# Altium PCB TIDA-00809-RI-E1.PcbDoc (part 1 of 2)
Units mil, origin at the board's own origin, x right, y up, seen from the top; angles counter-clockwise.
Board outline 5400 x 1000 mil, 2 copper layers (Top Layer, Bottom Layer), stack 62 mil thick; 167 components, 75 nets, 354 pads, 72 vias.
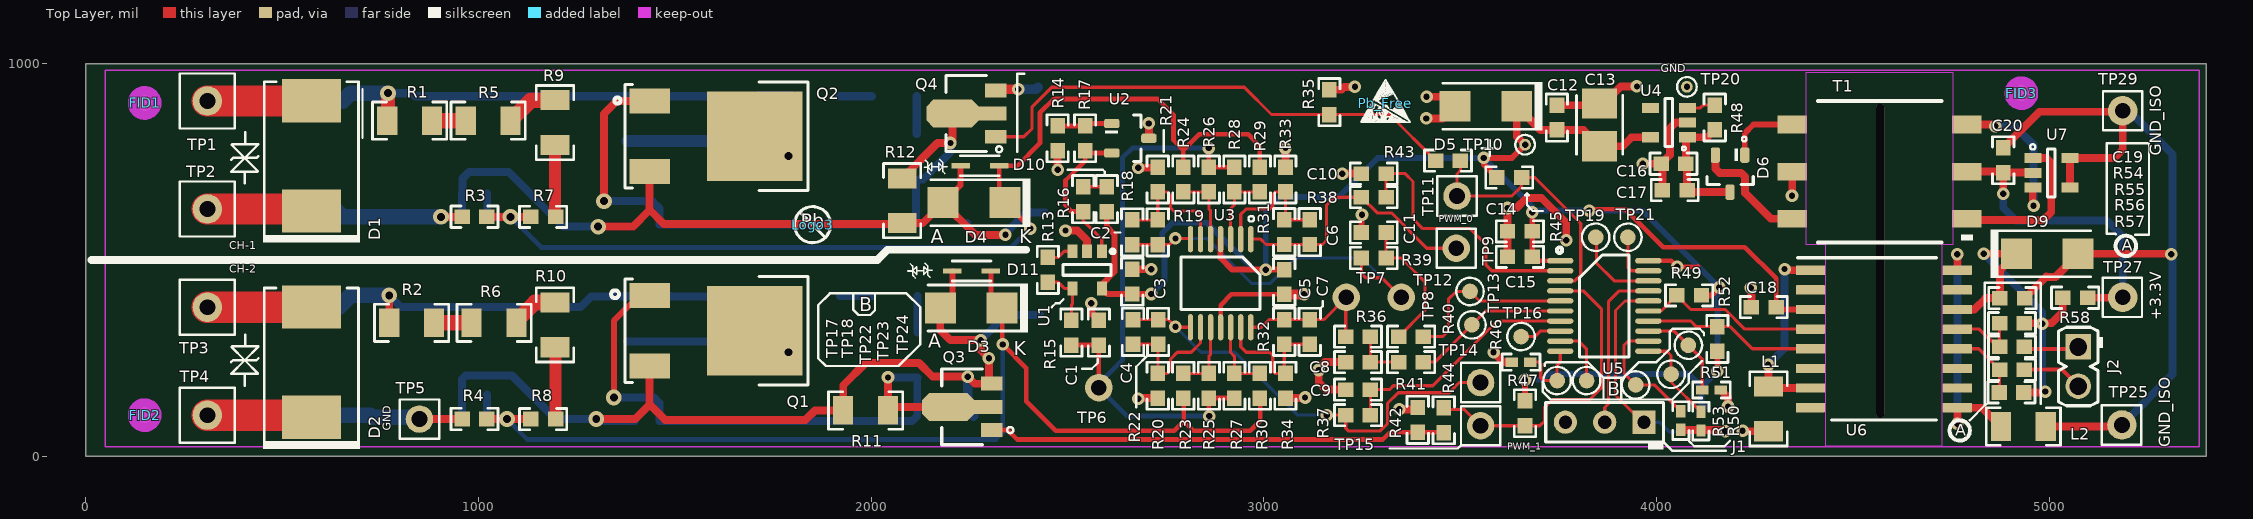
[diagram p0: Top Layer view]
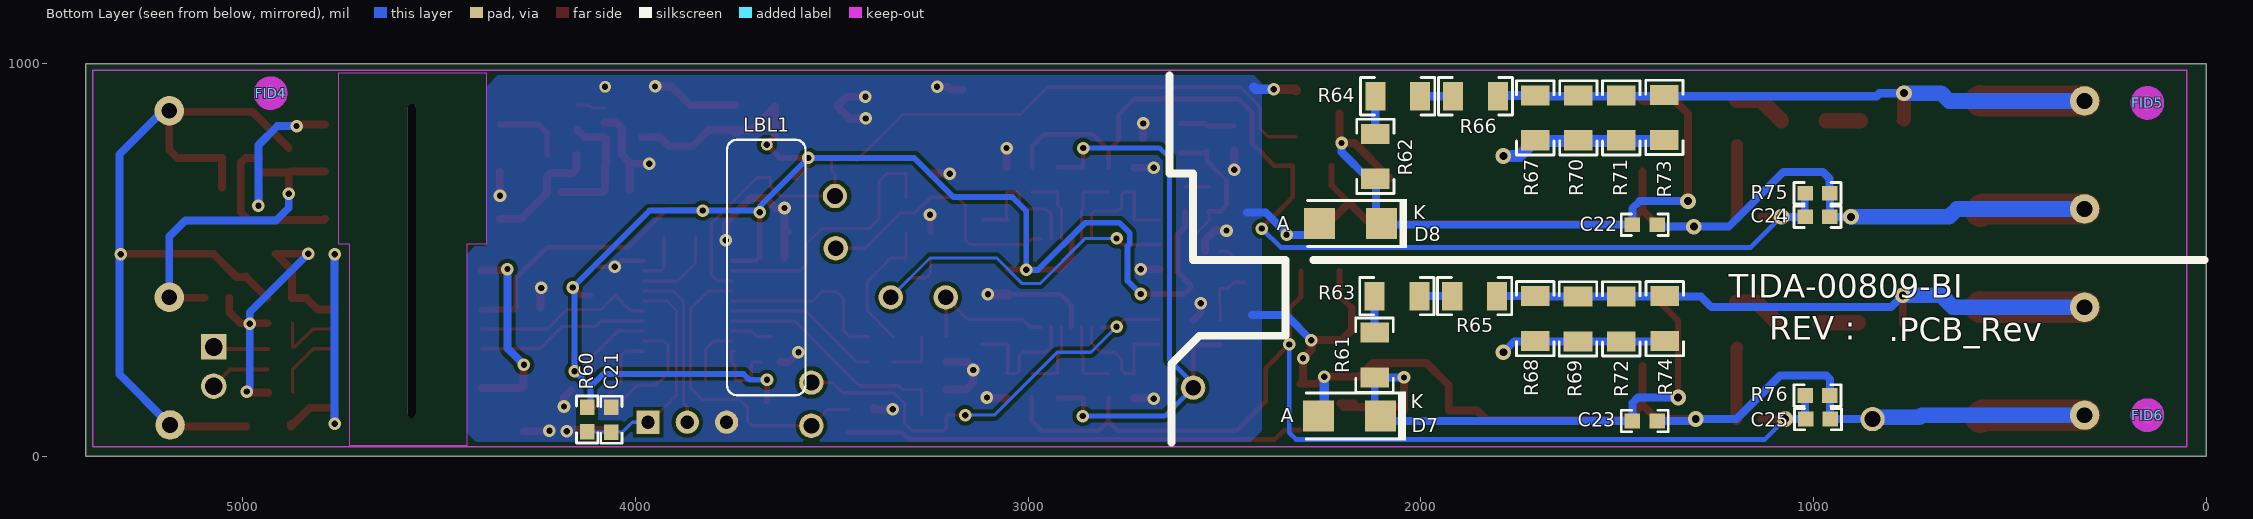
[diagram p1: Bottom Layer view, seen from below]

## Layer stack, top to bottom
Top Solder: solder mask 0.4, Solder Resist, Dk 3.5
Top Layer: signal copper 1.4
Dielectric1: core 59.2, FR-4, Dk 4.8
Bottom Layer: signal copper 1.4
Bottom Solder: solder mask 0.4, Solder Resist, Dk 3.5

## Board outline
0,0 5400,0 5400,1000 0,1000

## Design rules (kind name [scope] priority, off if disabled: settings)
AcuteAngle [All] p1: minimum=4.50000000000000E+0001 checktracksonly=FALSE
AssemblyTestPointUsage [All] p1: valid=2
Clearance "shape to track" [InPolygon vs IsTrack and IsSMTPin and IsVia] p1: gap=12
Clearance "Shape to Shape" [InPolygon vs InPolygon] p2: gap=25
Clearance "SMD to Via" [IsSMTPin vs IsVia] p3: gap=8
Clearance "Via to Via" [IsVia vs IsVia] p4: gap=12
Clearance [All] p5: gap=10
DiffPairsRouting [All] p1: maxlimit=100 minlimit=10 mostfreqgap=10 toplayer_minwidth=15 toplayer_maxwidth=15 toplayer_prefwidth=15 bottomlayer_minwidth=15 bottomlayer_maxwidth=15 bottomlayer_prefwidth=15 maxuncoupledlength=1000
FabricationTestPointUsage TestPointUsage [All] p1: valid=2 allowmultiple=FALSE
FabricationTestpoint Testpoint [All] p1: side=3 testpointundercomponent=TRUE minsize=40 maxsize=100 preferedsize=60 minholesize=0 maxholesize=40 preferedholesize=32 testpointgrid=1 allowsidetop=TRUE allowsidebottom=TRUE usegrid=TRUE gridtolerance=0.01
FanoutControl Fanout_LCC [IsLCC] p1: bgadir=Out bgaviamode=Centered fanoutstyle=Auto fanoutdirection=Alternating viagrid=1 // Fanout_LCC (Default Rule)
FanoutControl Fanout_BGA [IsBGA] p2: bgadir=Out bgaviamode=Centered fanoutstyle=Auto fanoutdirection=Alternating viagrid=1 // Fanout_BGA (Default Rule)
FanoutControl Fanout_Default [All] p4: bgadir=Out bgaviamode=Centered fanoutstyle=Auto fanoutdirection=Alternating viagrid=1 // Fanout_Default (Default Rule)
FanoutControl Fanout_Small [(CompPinCount < 5)] p5: bgadir=Out bgaviamode=Centered fanoutstyle=Auto fanoutdirection=OutThenIn viagrid=1 // Fanout_Small (Default Rule)
HoleSize [All] p1: absolutevalues=TRUE maxlimit=1000 minlimit=8 maxpercent=80.000 minpercent=20.000
MinimumAnnularRing [All] p1: minimumring=7
MinimumAnnularRing MinimumAnnularRing_ThermalPadVias [IsVia and InAnyComponent] p2: minimumring=5.91
MinimumSolderMaskSliver MinimumSolderMaskSliver_Logo [InComponentClass('Logo') vs InComponentClass('Logo')] p1: minsoldermaskwidth=0.7
MinimumSolderMaskSliver [All] p2: minsoldermaskwidth=3.94
PlaneConnect [All] p1: planeconnectstyle=Relief reliefexpansion=10 reliefentries=4 reliefconductorwidth=10 reliefairgap=10
PolygonConnect [All] p1: connectstyle=Direct reliefconductorwidth=10 reliefentries=4 polygonreliefangle="90 Angle" airgapwidth=10
RoutingVias ThermalPadVias [IsVia and InAnyComponent] p1: holewidth=8 width=20 viastyle="Through Hole" minholewidth=8 minwidth=20 maxholewidth=12 maxwidth=24
RoutingVias [All] p2: holewidth=16 width=32 viastyle="Through Hole" minholewidth=12 minwidth=26 maxholewidth=31.5 maxwidth=62.99
SMDToCorner [All] p1: distance=30000
ShortCircuit ShortCircuit_1 [InNet('GND') vs InNet('GND1')] p1: allowed=TRUE
SilkToSilkClearance [All] p1: silktosilkclearance=5
SilkToSolderMaskClearance SilkscreenOverComponentPads [IsPad] p1: minsilkscreentomaskgap=5 clearancetoexposedcopper=TRUE
SolderMaskExpansion [All] p1: expansion=2.5
UnpouredPolygon [All] p1: allowunpoured=FALSE
Width [All] p1: maxlimit=100 minlimit=8 preferedwidth=20 checkconnectedcopper=TRUE
15 further rules are at their usual default settings.

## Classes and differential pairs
component class "Pg3 MICROCONTROLLER": C12 C13 C14 C15 C16 C17 C18 C19 C20 C21 D5 D6 D9 J1 J2 L1 L2 R40 R41 R45 R46 R47 R48 R49 R50 R51 R52 R53 R54 R55 R56 R57 R58 R60 T1 TP10 TP12 TP13 TP16 TP17 TP18 TP19 TP21 TP22 TP23 TP24 TP25 TP27 TP29 U4 U5 U6 U7
component class Label: LBL1
component class AssemblyNote: ZZ1 ZZ2 ZZ3 ZZ4
component class Header: J1 J2
component class "Pg 5 Hardware_ANSI-B": !PCB1 FID1 FID2 FID3 FID4 FID5 FID6 LBL1 Logo3 Pb_Free ZZ1 ZZ2 ZZ3 ZZ4
component class FiducialMark: FID1 FID2 FID3 FID4 FID5 FID6
component class "Pg 4 BINARY INPUTS": C1 C2 C3 C4 C5 C6 C7 C8 C9 C10 C11 C22 C23 C24 C25 D1 D2 D3 D4 D7 D8 D10 D11 Q1 Q2 Q3 Q4 R1 R2 R3 R4 R5 R6 R7 R8 R9 R10 R11 R12 R13 R14 R15 R16 R17 R18 R19 R20 R21 R22 R23 R24 R25 R26 R27 R28 R29 R30 R31 R32 R33 R34 R35 R36 R37 R38 R39 R42 R43 R44 R61 R62 R63 R64 R65 R66 R67 R68 R69 R70 R71 R72 R73 R74 R75 R76 TP1 TP2 TP3 TP4 TP5 TP6 TP7 TP8 TP9 TP11 TP14 TP15 TP20 U1 U2 U3

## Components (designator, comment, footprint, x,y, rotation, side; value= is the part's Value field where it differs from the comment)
C1 "06033C104JAT2A" 0603 2580,315 r270 top
C2 "06035A101FAT2A" 0603 2665,570.5 r90 top
C3 "06033C104JAT2A" 0603 2665,445 r270 top
C4 "06035A101FAT2A" 0603 2667,317 r270 top
C5 "06033C104JAT2A" 0603 3052,444 r90 top
C6 "06035A101FAT2A" 0603 3117,571 r90 top
C7 "06035A101FAT2A" 0603 3117,317 r270 top
C8 "C1608C0G1E103J" 0603 3240,240 r0 top
C9 "C1608C0G1E103J" 0603 3240,170 r0 top
C10 "C1608C0G1E103J" 0603 3280,720 r0 top
C11 "C1608C0G1E103J" 0603 3280,570 r0 top
C12 "C0603C104K5RACTU" 0603 3746.36,862.64 r90 top
C13 "T491B106K016AT" 3528-21 3855,844 r90 top
C14 "C1608X7R1C105K" 0603 3652,573 r180 top
C15 "C0603C104K5RACTU" 0603 3652,508 r0 top
C16 "C0603C104K5RACTU" 0603 4043.32,745.02 r180 top
C17 "C1608X7R1C105K" 0603 4046.32,678.02 r180 top
C18 "C0603C104K5RACTU" 0603 4273,380 r0 top
C19 "C0603C104K5RACTU" 0603 4906,403 r0 top
C20 "C1608X7R1C105K" 0603 4883,754 r90 top
C21 "GRM188R71H471KA01D" 0603 4061.3,93.19 r90 bottom
C22 "UMK107AB7105KA-T" 0603 1430,590 r0 bottom
C23 "UMK107AB7105KA-T" 0603 1430,90 r0 bottom
C24 "C1608C0G1H102J" 0603 990,610 r0 bottom
C25 "C1608C0G1H102J" 0603 989,95 r0 bottom
D1 "SMCJ400CA" SMC 575,765 r90 top
D2 "SMCJ400CA" SMC 575,240 r90 top
D3 "PTZTE255.1B" SMA 2255,378 r180 top
D4 "PTZTE255.1B" SMA 2262,646 r180 top
D5 "PTZTE253.9B" SMA 3565.36,891.64 r180 top
D6 "BAT54C-7-F" SOT-23 4187.32,720.02 r270 top
D7 "PTZTE2515B" SMA 2182,103 r0 bottom
D8 "PTZTE2515B" SMA 2178.98,593 r0 bottom
D9 "PTZTE253.9B" SMA 4995,516 r0 top
D10 "PESD3V3L1BA" DIO_SOD323 2277,740 r180 top
D11 "PESD3V3L1BA" DIO_SOD323 2256,472 r180 top
FID1 "Fiducial" Fiducial10-20 150,900 r0 top
FID2 "Fiducial" Fiducial10-20 150,105 r0 top
FID3 "Fiducial" Fiducial10-20 4929,925 r0 top
FID4 "Fiducial" Fiducial10-20 4929,925 r180 bottom
FID5 "Fiducial" Fiducial10-20 150,900 r180 bottom
FID6 "Fiducial" Fiducial10-20 150,105 r180 bottom
J1 "800-10-003-10-001000" Mill-Max_800-10-003-10-001000 3868,87 r180 top
J2 "61300211121" WURTH_61300211121 5074,228.84 r270 top
L1 "HZ1206D102R-10" 1206 4285,121 r90 top
L2 "HZ1206D102R-10" 1206 4934,76 r0 top
LBL1 "Size: 0.65\" x 0.20 \"" Label_650x200 3667,481 r270 bottom
Logo3 "Pb-Free Symbol" Pb-Free_Overlay_Small 1851,590 r0 top
Pb_Free "ESD Susceptible" ESD_Overlay_small 3309,899 r0 top
Q1 "AOD2N60" DPAK_G 1570,320 r0 top
Q2 "AOD2N60" DPAK_G 1570,815 r0 top
Q3 "FCX458" SOT-89-3 2232,126 r180 top
Q4 "FCX458" SOT-89-3 2243,873 r180 top
R1 "RC1206FR-07100KL" 1206 825,855 r0 top
R2 "RC1206FR-07100KL" 1206 830,340 r0 top
R3 "RC0603FR-072K2L" 0603 990,610 r0 top
R4 "RC0603FR-072K2L" 0603 990,95 r0 top
R5 "RC1206FR-07100KL" 1206 1025,855 r0 top
R6 "RC1206FR-07100KL" 1206 1040,340 r0 top
R7 "RC0603JR-070RL" 0603 1165,610 r180 top
R8 "RC0603JR-070RL" 0603 1165,95 r180 top
R9 "RC1206FR-07100KL" 1206 1195,850 r270 top
R10 "RC1206FR-07100KL" 1206 1195,335 r270 top
R11 "CRCW1206100KFKEA" 1206 1986,117 r0 top
R12 "CRCW1206100KFKEA" 1206 2079,651 r90 top
R13 "RC0603JR-070RL" 0603 2450,475 r270 top
R14 "CRCW060310K0FKEA" 0603 2475,810 r90 top
R15 "CRCW0603100RFKEA" 0603 2510,315 r270 top
R16 "CRCW0603470RJNEA" 0603 2540,655 r90 top
R17 "CRCW060330K0JNEA" 0603 2545,810 r270 top
R18 "CRCW0603100RFKEA" 0603 2600,655 r90 top
R19 "CRCW0603160KFKEA" 0603 2730,570.5 r90 top
R20 "RC0603FR-0747KL" 0603 2730,180 r90 top
R21 "RC0603FR-0747KL" 0603 2730,705 r270 top
R22 "RC0603FR-0747KL" 0603 2731,317 r90 top
R23 "RC0603FR-0747KL" 0603 2795,180 r90 top
R24 "RC0603FR-0747KL" 0603 2795,705 r270 top
R25 "RC0603FR-0747KL" 0603 2860,180 r90 top
R26 "CRCW0603160KFKEA" 0603 2860,705 r270 top
R27 "CRCW0603160KFKEA" 0603 2925,180 r90 top
R28 "RC0603FR-0747KL" 0603 2925,705 r270 top
R29 "RC0603FR-0747KL" 0603 2990,705 r90 top
R30 "RC0603FR-0747KL" 0603 2990,180 r90 top
R31 "RC0603FR-0747KL" 0603 3052,571 r90 top
R32 "CRCW0603160KFKEA" 0603 3052,317 r270 top
R33 "RC0603FR-0747KL" 0603 3055,705 r90 top
R34 "RC0603FR-0747KL" 0603 3055,180 r90 top
R35 "CRCW0603100KFKEA" 0603 3167,902 r270 top
R36 "CRCW060310R0FKEA" 0603 3240,305 r0 top
R37 "CRCW060310R0FKEA" 0603 3240,105 r0 top
R38 "CRCW060310R0FKEA" 0603 3280,660 r0 top
R39 "CRCW060310R0FKEA" 0603 3280,505 r0 top
R40 "CRCW06030000Z0EA" 0603 3375,305 r0 top
R41 "CRCW06030000Z0EA" 0603 3375,240 r0 top
R42 "CRCW0603100KFKEA" 0603 3392,93 r270 top
R43 "CRCW06032K61FKEA" 0603 3469,753 r180 top
R44 "CRCW06032K61FKEA" 0603 3458,92 r270 top
R45 "CRCW060310K0FKEA" 0603 3625,710 r180 top
R46 "RC0402JR-070RL" 0402 3655,240 r0 top
R47 "CRCW060310K0FKEA" 0603 3665,110 r90 top
R48 "CRCW060310K0FKEA" 0603 4148.32,863.02 r270 top
R49 "CRCW06031K50FKEA" 0603 4083,410 r0 top
R50 "RC0402JR-070RL" 0402 4062,91 r90 top
R51 "RC0402JR-070RL" 0402 4140,169 r180 top
R52 "CRCW06031K50FKEA" 0603 4155,299 r270 top
R53 "RC0402JR-070RL" 0402 4113,89.62 r90 top
R54 "CRCW06031K50FKEA" 0603 4905,338.84 r0 top
R55 "CRCW06030000Z0EA" 0603 4905,278.84 r0 top
R56 "CRCW06030000Z0EA" 0603 4905,220.84 r0 top
R57 "CRCW06031K50FKEA" 0603 4904,162.84 r0 top
R58 "CRCW06030000Z0EA" 0603 5066,404 r0 top
R60 "RC0603JR-0747KL" 0603 4123,94 r90 bottom
R61 "RC1206FR-07100KL" 1206 2118,258 r90 bottom
R62 "RC1206FR-07100KL" 1206 2116,764 r270 bottom
R63 "RC1206FR-07100KL" 1206 2061,408 r180 bottom
R64 "RC1206FR-07100KL" 1206 2059,917 r0 bottom
R65 "RC1206FR-07100KL" 1206 1863,408 r0 bottom
R66 "RC1206FR-07100KL" 1206 1861,917 r0 bottom
R67 "MCR18ERTF1002" 1206 1709,862 r90 bottom
R68 "MCR18ERTF1002" 1206 1709,351 r90 bottom
R69 "MCR18ERTF1002" 1206 1600,350 r90 bottom
R70 "MCR18ERTF1002" 1206 1599,862 r90 bottom
R71 "MCR18ERTF1002" 1206 1490,862 r90 bottom
R72 "MCR18ERTF1002" 1206 1490,350 r90 bottom
R73 "MCR18ERTF1002" 1206 1380,863 r90 bottom
R74 "MCR18ERTF1002" 1206 1379,351 r90 bottom
R75 "RC0603FR-072K2L" 0603 990,670 r0 bottom
R76 "RC0603FR-072K2L" 0603 990,155 r0 bottom
T1 "#NAME?" Wurth_750313734 4568,725 r180 top
TP1 "TP-5001-BLACK" TH-40 310,905 r0 top
TP2 "TP-5001-BLACK" TH-40 310,630 r0 top
TP3 "TP-5001-BLACK" TH-40 310,380 r0 top
TP4 "TP-5001-BLACK" TH-40 310,105 r270 top
TP5 "TP-040_RND" TP-040_RND 850,95 r90 top
TP6 "TP-040_RND" TP-040_RND 2580,175 r90 top
TP7 "TP-040_RND" TP-040_RND 3210,405 r90 top
TP8 "TP-040_RND" TP-040_RND 3350,405 r90 top
TP9 "TP-040_RND" TP-040_RND 3490,530 r90 top
TP10 "TP1_PD40_D0.5_S50" TP1_PD40_D0.5_S50 3665.36,793.64 r90 top
TP11 "TP-040_RND" TP-040_RND 3492,663 r90 top
TP12 "PAD_230UM" PAD_230UM 3525,420 r90 top
TP13 "PAD_230UM" PAD_230UM 3530,335 r90 top
TP14 "TP-040_RND" TP-040_RND 3552,188 r90 top
TP15 "TP-040_RND" TP-040_RND 3552,78 r90 top
TP16 "PAD_230UM" PAD_230UM 3655,305 r90 top
TP17 "PAD_230UM" PAD_230UM 3747,193 r90 top
TP18 "PAD_230UM" PAD_230UM 3822,193 r90 top
TP19 "PAD_230UM" PAD_230UM 3845,558 r90 top
TP20 "TP1_PD40_D0.5_S50" TP1_PD40_D0.5_S50 4077.32,941.02 r90 top
TP21 "PAD_230UM" PAD_230UM 3927,558 r90 top
TP22 "PAD_230UM" PAD_230UM 3947,182 r90 top
TP23 "PAD_230UM" PAD_230UM 4037,209 r90 top
TP24 "PAD_230UM" PAD_230UM 4081,283 r90 top
TP25 "TP-5001-BLACK" TH-40 5185,80 r0 top
TP27 "TP-5001-BLACK" TH-40 5187,405 r0 top
TP29 "TP-5001-BLACK" TH-40 5187,880 r0 top
U1 "LMV551MF" MF05A_L 2550,475 r270 top
U2 "LM4041BIDBZ" SOT-23 2660,810 r0 top
U3 "LMV614MT" PW0014A_N 2890,440.98 r270 top
U4 "TPS70933DBVT" DBV0005A_N 4031.32,850.02 r180 top
U5 "MSP430G2332IPW20" PW0020A_N 3867,383 r0 top
U6 "ISO7820DWR" DW0016B_N 4579,299 r0 top
U7 "SN6501DBV" DBV0005A_N 5005.24,722 r0 top
ZZ1 "This Assembly Note is for PCB labels only" AssemblyNoteLabel -184,1762 r0 top
ZZ2 "These assemblies are ESD sensitive, ESD precautions shall be observed." AssemblyNote -184,1687 r0 top
ZZ3 "These assemblies must be clean and free from flux and all contaminants. Use of no clean flux is not acceptable." AssemblyNote -184,1602 r0 top
ZZ4 "These assemblies must comply with workmanship standards IPC-A-610 Class 2, unless otherwise specified." AssemblyNote -184,1527 r0 top

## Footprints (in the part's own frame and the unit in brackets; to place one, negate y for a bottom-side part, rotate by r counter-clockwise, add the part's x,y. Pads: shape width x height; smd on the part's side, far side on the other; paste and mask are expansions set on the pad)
0402 [mm] "0402 from SM-752 data"
  rect 0.8x0.6 smd: 1(-0.6,0) 2(0.6,0)
  silkscreen extent -1.22,-0.52 1.22,0.52, body extent -0.55,-0.3 0.55,0.3, height 0.6
0603 [mm] "0603 from SM-752 data"
  rect 1x0.95 smd: 1(-0.8,0) 2(0.8,0)
  silkscreen extent -1.52,-0.69 1.52,0.69, body extent -0.87,-0.47 0.87,0.47, height 0.85
1206 [mm] "1206 from SM-752 data"
  rect 1.3x1.85 smd: 1(-1.45,0) 2(1.45,0)
  silkscreen extent -2.4,-1.21 2.4,1.21, body extent -1.7,-0.9 1.7,0.9, height 1.35
3528-21 [mm] "Medium Density IPC, based on SM-782 section 8.4"
  rect 1.95x2.25 smd: 1(-1.375,0) 2(1.375,0)
  silkscreen extent -1.9,-1.5 1.9,1.5, body extent -1.85,-1.5 1.85,1.5, height 2.1
AssemblyNote [mil] "Assembly Note"
AssemblyNoteLabel [mil] "Assembly Note for PCB Labels"
DBV0005A_N [mm] "SOT23, 5-Leads, Body 2.9x1.6mm, Pitch 0.95mm, Lead Span 2.8mm, IPC Medium Density"
  rect 1.1x0.65 smd: 1(-1.2,0.95) 2(-1.2,0) 3(-1.2,-0.95) 4(1.2,-0.95) 5(1.2,0.95)
  silkscreen extent -0.25,-1.55 0.25,1.55, body extent -1.42,-1.46 1.42,1.46, height 1.08
DIO_SOD323 [mm] "TVS DIODE, SOD323, SMT"
  rect 1.2x0.35 smd: 1(-1.25,0) 2(1.25,0)
  silkscreen extent -1.25,-0.65 1.25,0.65, body extent -1.25,-0.63 1.25,0.63, height 1.1
DPAK_G [mm] "D-PAK, 3-Pads, Body 6.22x6.73mm (max), TO-252AA using nominal STEP model"
  rect 6.2x5.8 smd paste-2.9: D(3.4,0)
  rect 2.6x1.6 smd: G(-3.4,2.28) S(-3.4,-2.28)
  silkscreen extent -5.89,-3.5 6.83,3.5, body extent -3.86,-3.29 5.84,3.29, height 2.48
DW0016B_N [mm] "SOIC, 16-Leads, Body 10.5x7.6mm, Pitch 1.27mm, IPC Medium Density"
  rrect17% 1.9x0.6 smd: 1(-4.75,4.445) 2(-4.75,3.175) 3(-4.75,1.905) 4(-4.75,0.635) 5(-4.75,-0.635) 6(-4.75,-1.905) 7(-4.75,-3.175) 8(-4.75,-4.445) 9(4.75,-4.445) 10(4.75,-3.175) 11(4.75,-1.905) 12(4.75,-0.635) 13(4.75,0.635) 14(4.75,1.905) 15(4.75,3.175) 16(4.75,4.445)
  silkscreen extent -5.6,-5.25 3.4,5.25, body extent -5.17,-5.15 5.17,5.15, height 2.59
ESD_Overlay_small [mil]
  silkscreen extent -62,-48 64,61
Fiducial10-20 [mm]
  round 1 smd mask+0.5: 1(0,0)
  Top Layer keep-out circle w1.178: c0,0 r0.5
Label_650x200 [mil] "Thermal Transfer Label"
  silkscreen extent -325,-100 325,100, body extent -326,-101 326,101, height 1
MF05A_L [mm] "SOT23, 5-Leads, Body 2.9x1.6mm, Pitch 0.95mm, Lead Span 2.8mm, IPC High Density"
  rect 0.9x0.65 smd: 1(-1.2,0.95) 2(-1.2,0) 3(-1.2,-0.95) 4(1.2,-0.95) 5(1.2,0.95)
  silkscreen extent -1.32,-1.55 0.35,1.77, body extent -0.9,-1.55 0.9,1.55, height 1.19
Mill-Max_800-10-003-10-001000 [mm] "Mill-Max"
  rect 1.5x1.5 hole 0.85: 1(-2.54,0)
  round 1.5 hole 0.85: 2(0,0) 3(2.54,0)
  silkscreen extent -3.81,-1.27 3.81,1.78, body extent -3.81,-1.27 3.81,1.27, height 8.13
PAD_230UM [mil]
  round 40 smd: 1(0,0)
  silkscreen extent -35,-35 35,35
Pb-Free_Overlay_Small [mil]
  silkscreen extent -46,-46 46,46
PW0014A_N [mm] "TSOP, 14-Leads, Body 5x4.4mm, Pitch 0.65mm, IPC Medium Density"
  oval 1.7x0.35 smd: 1(-2.85,1.95) 2(-2.85,1.3) 3(-2.85,0.65) 4(-2.85,0) 5(-2.85,-0.65) 6(-2.85,-1.3) 7(-2.85,-1.95) 8(2.85,-1.95) 9(2.85,-1.3) 10(2.85,-0.65) 11(2.85,0) 12(2.85,0.65) 13(2.85,1.3) 14(2.85,1.95)
  silkscreen extent -1.7,-2.55 1.7,2.55, body extent -3.21,-2.5 3.21,2.5, height 0.98
PW0020A_N [mm] "TSOP, 20-Leads, Body 6.5x4.4mm, Pitch 0.65mm, IPC Medium Density"
  oval 1.7x0.35 smd: 1(-2.85,2.925) 2(-2.85,2.275) 3(-2.85,1.625) 4(-2.85,0.975) 5(-2.85,0.325) 6(-2.85,-0.325) 7(-2.85,-0.975) 8(-2.85,-1.625) 9(-2.85,-2.275) 10(-2.85,-2.925) 11(2.85,-2.925) 12(2.85,-2.275) 13(2.85,-1.625) 14(2.85,-0.975) 15(2.85,-0.325) 16(2.85,0.325) 17(2.85,0.975) 18(2.85,1.625) 19(2.85,2.275) 20(2.85,2.925)
  silkscreen extent -1.6,-3.3 1.6,3.3, body extent -3.21,-3.25 3.21,3.25, height 0.99
SMA [mm] "Molded Diode, 2-Leads, Body 4.3x2.6mm, IPC Medium Density, based on OnSemi component dimensions and land pattern"
  rect 2x2 smd: 1(-2,0) 2(2,0)
  silkscreen extent -3.66,-1.57 2.79,1.57, body extent -2.6,-1.3 2.6,1.3, height 2.42
SMC [mil] "Molded Diode, 2-Leads, Body 6.9x5.8mm, IPC Medium Density, based on OnSemi component dimensions and land patterns"
  rect 110x150 smd: 1(-140.49,0) 2(140.49,0)
  silkscreen extent -221,-123 189,124, body extent -156,-116 156,116, height 91
SOT-23 [mm] "SOT23, 3-Leads, Body 2.9x1.3mm, Pitch 0.95mm, Lead Span 2.5mm, IPC Medium Density"
  rrect50% 1x0.6 smd: 1(-1.2,0.95) 2(-1.2,-0.95) 3(1.2,0)
  silkscreen extent -1.62,-1.5 0.7,1.5, body extent -1.16,-1.45 1.21,1.45, height 1
SOT-89-3 [mm] "SOT, 3-Leads, Body 4.6 x 2.6 mm, Pitch 1.5mm"
  rect 1.4x0.9 smd: 1(-1.9,1.5) 3(-1.9,-1.5)
  rect 1.8x0.9 smd: 2(-1.7,0)
  oct 3.4x1.8 smd: 4(0.9,0)
  silkscreen extent -1.3,-2.45 1.33,2.45, body extent -2.42,-2.28 1.83,2.32, height 1.62
TH-40 [mil]
  round 75 hole 40: 1(0,0)
TP1_PD40_D0.5_S50 [mil]
  round 30 hole 16: 1(0,0)
  silkscreen extent -25,-25 25,25
TP-040_RND [mil]
  round 70 / inner round 62 / far side round 62 hole 40: 1(0,0)
Wurth_750313734 [mil]
  rect 75x45 smd: 1(-222.5,120) 2(-222.5,0) 3(-222.5,-120) 4(222.5,-120) 5(222.5,0) 6(222.5,120)
  silkscreen extent -238,-180 157,180, body extent -240,-180 157,180, height 300
WURTH_61300211121 [mm] "Header, 2.54mm, 2x1, TH"
  rect 1.65x1.65 hole 1.15: 1(-1.27,0)
  round 1.65 hole 1.15: 2(1.27,0)
  silkscreen extent -2.54,-1.27 2.54,1.6, body extent -2.54,-1.27 2.54,1.27, height 8.54

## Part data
C1 C3 C5: "CAP, CERM, 0.1uF, 25V, +/-5%, X7R, 0603"
C2 C4 C6 C7: "CAP, CERM, 100pF, 50V, +/-1%, C0G/NP0, 0603"
C8 C9 C10 C11: "CAP, CERM, 0.01uF, 25V, +/-5%, C0G/NP0, 0603"
C12 C15 C16 C18 C19: "CAP, CERM, 0.1uF, 50V, +/-10%, X7R, 0603"
C13: library part 293D106X9016B2TE3, "CAP, TA, 10 µF, 16 V, +/- 10%, 2 ohm, SMD"
C14 C17 C20: "CAP, CERM, 1uF, 16V, +/-10%, X7R, 0603"
C21: "CAP, CERM, 470 pF, 50 V, +/- 10%, X7R, 0603"
C22 C23: "CAP, CERM, 1 µF, 50 V, +/- 10%, X7R, 0603"
C24 C25: "CAP, CERM, 1000pF, 50V, +/-5%, C0G/NP0, 0603"
D1 D2: library part SMCJ15CA, "TVS DIODE 400VWM 648VC SMC"
D3 D4: library part BZT52C3V3T-7, "DIODE ZENER 5.4V 1W PMDS"
D5 D9: library part PTZTE255.6B, "DIODE ZENER 4.1V 1W PMDS"
D6: "Diode, Schottky, 30V, 0.2A, SOT-23"
D7 D8: library part BZT52C3V3T-7, "DIODE ZENER 15.4V 1W PMDS"
D10 D11: "DIODE, TVS, BIDIRECTIONAL, 3.3VWM, 26VC, SOD323"
FID1 FID2 FID3 FID4 FID5 FID6: "Fiducial mark.  There is nothing to buy or mount."
J1: "Header, 100mil, 3x1, TH"
J2: "Header, 2.54 mm, 2x1, Gold, TH"
L1 L2: "Ferrite Bead, 1000 ohm @ 100 MHz, 0.4 A, 1206"
LBL1: library part THT-14-423-10, "Thermal Transfer Printable Labels, 0.650\" W x 0.200\" H - 10,000 per roll"
Logo3: library part Pb-Free
Pb_Free: library part ESD_Susceptible, "ESD Susceptible Symbol"
Q1 Q2: library part DN2450K4-G, "MOSFET N-CH 600V 2A TO252"
Q3 Q4: library part "FCX458TA, Diodes Inc.", "Transistor, NPN, 400V, 500mA, SOT-89"
R1 R2 R5 R6 R9 R10 R61 R62 R63 R64 R65 R66: "RES, 100 k, 1%, 0.25 W, 1206"
R3 R4 R75 R76: "RES, 2.20 k, 1%, 0.1 W, 0603"
R7 R8 R13 R40 R41 R55 R56 R58: "RES, 0, 5%, 0.1 W, 0603"
R11 R12: "RES, 100k ohm, 1%, 0.25W, 1206"
R14 R45 R47 R48: "RES, 10.0k ohm, 1%, 0.1W, 0603"
R15 R18: "RES, 100 ohm, 1%, 0.1W, 0603"
R16: "RES, 470 ohm, 5%, 0.1W, 0603"
R17: "RES, 30k ohm, 5%, 0.1W, 0603"
R19 R26 R27 R32: "RES, 160 k, 1%, 0.1 W, 0603"
R20 R21 R22 R23 R24 R25 R28 R29 R30 R31 R33 R34: "RES, 47.0 k, 1%, 0.1 W, 0603"
R35 R42: "RES, 100k ohm, 1%, 0.1W, 0603"
R36 R37 R38 R39: "RES, 10.0, 1%, 0.1 W, 0603"
R43 R44: "RES, 2.61k ohm, 1%, 0.1W, 0603"
R46 R50 R51 R53: library part CRCW06030000Z0EA, "RES, 0, 5%, 0.063 W, 0402"
R49 R52 R54 R57: "RES, 1.50k ohm, 1%, 0.1W, 0603"
R60: "RES, 47 k, 5%, 0.1 W, 0603"
R67 R68 R69 R70 R71 R72 R73 R74: library part RC1206FR-0727KL, "RES SMD 10K OHM 1% 1/4W 1206"
T1: library part 750313734_TRANSFORMER, "TRANSFORMER SMD"
TP1 TP2 TP3 TP4 TP25 TP27 TP29: "Test Point,  Black, Thru Hole Color Keyed"
TP5 TP6 TP7 TP8 TP9 TP11 TP14 TP15: "Test Point, O.040 Hole"
TP10 TP20: library part TP-040_RND, "Test Point 40mil pad 20mil drill"
TP12 TP13 TP16 TP17 TP18 TP19 TP21 TP22 TP23 TP24: "Pad, SMT 0.23 mm"
U1: "3MHz Single Micropower R-R Out Op Amp"
U2: "IC, Micropower Shunt Voltage Reference 100 ppm/°C, 45µA-12mA,  Adjustable"
U3: "Quad 1.4 MHz, Low Power General Purpose, 1.8V Op Amp, PW0014A"
U4: "IC REG LDO 3.3V 0.15A SOT23-5"
U5: "IC MCU 16BIT 4KB FLASH 20TSSOP"
U6: "High-Performance, 8000 VPK Reinforced Dual Channel Digital Isolator, DW0016B"
U7: "Transformer Driver for Isolated Power Supplies, DBV0005A"
ZZ1: library part AssemblyNoteLabel
ZZ2 ZZ3 ZZ4: library part AssemblyNote

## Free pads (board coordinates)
  oval 20x800 hole 20 slot 800 at 90 deg unplated paste+5 mask+5: 0(4570,498)

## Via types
v1: diameter 32, hole 16, Top Layer to Bottom Layer, tented both sides, 61 vias
v2: diameter 40, hole 20, Top Layer to Bottom Layer, tented both sides, 11 vias

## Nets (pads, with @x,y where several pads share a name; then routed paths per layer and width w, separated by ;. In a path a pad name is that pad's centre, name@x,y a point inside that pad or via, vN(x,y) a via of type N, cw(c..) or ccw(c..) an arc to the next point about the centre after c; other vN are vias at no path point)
+3.3V: C20.1 R58.2 T1.2 TP27.1 U7.2 | length 838.6
  Top Layer w20: T1.2@4790.5,725 4877.5,725 4881.5,721 C20.1@4883,722.5 ; v1(4883,669) C20.1@4883,722.5 ; U7.2@4958,722 4957.5,722.5 C20.1@4883,722.5 ; R58.2@5097.5,404 5186,404 TP27.1@5187,405
  Bottom Layer w20: v1(4883,669) 4883,633 4915,601 5146,601 5187,560 TP27.1@5187,405
+3.3VSEC: C3.2 C5.2 C12.1 C13.1 C14.1 C15.2 C18.2 D5.1 R18.1 R45.2 R47.2 R49.2 R52.2 R60.2 TP10.1 U1.5 U3.4 U4.5 U5.1 U6.3 | length 5114.1
  Top Layer w12: C15.2@3683.5,508 3693.34,498.16 U5.1@3754.8,498.16 ; v1@3832.5,629.5 3920.5,629.5 4017.25,532.75 4225,532.75 4304.5,453.25 C18.2@4304.5,380
  Top Layer w15: R18.1@2600,623.5 2600,585 2620,565 2620,470 2587.4,437.4 U1.5@2587.4,427.76 2601.65,413.5 C3.2@2665,413.5 v1(2713.5,413.5) ; U3.4@2890,553.19 2890,505 2919.5,475.5 C5.2@3052,475.5 ; R45.2@3593.5,710 3560,743.5 v1(3560,760) 3631.72,760 TP10.1@3665.36,793.64 ; R47.2@3665,141.5 v1(3665,195) ; C15.2@3683.5,508 C14.1@3683.5,573 v1(3683.5,621.5) ; R49.2@4114.5,410 4140,410 v1(4160,430) ; v1(4155,217) R52.2@4155,267.5 ; C18.2@4304.5,380 4310.5,374 U6.3@4391.99,374
  Top Layer w20: TP10.1@3665.36,793.64 3644.1,814.9 D5.1@3644.1,891.64 3704.6,831.14 C12.1@3746.36,831.14 3813.72,831.14 C13.1@3855,789.87 3913.87,789.87 3936.62,812.62 U4.5@3984.07,812.62 ; C12.1@3741.68,824.14 C12.1@3745.36,824.14
  Bottom Layer w15: v1(2713.5,413.5) 2747,447 2747,535.62 2741.5,541.12 2741.5,568.88 2767.62,595 2855,595 2975,475 v1(3005,475) 3005,625 3040,660 3190,660 3290,760 v1(3560,760) 3683.5,636.5 v1(3683.5,621.5) 3687.99,626 v1(3829,626) 3964,626 v1(4160,430) 4155,425 v1(4155,217) 4115,177 ; v1(3665,195) 3710,195 3725,210 4082,210 4115,177 ; R60.2@4123,125.5 4115,133.5 4115,177
ADC_0: C10.2 R38.2 U5.2 | length 692.2
  Top Layer w8: R38.2@3311.5,660 C10.2@3311.5,720 3360,720 3380,700 3380,605 3405,580 3525,580 3565,540 3565,487.57 3580,472.57 U5.2@3754.8,472.57
ADC_1: C11.2 R39.2 R40.1 | length 355.9
  Top Layer w8: C11.2@3311.5,570 R39.2@3311.5,505 3350,505 3362,493 3362,492.54 3410,444.54 3410,371.5 R40.1@3343.5,305
ADC_2: C8.2 R36.2 R41.1 | length 132
  Top Layer w8: C8.2@3271.5,240 R41.1@3343.5,240 ; C8.2@3271.5,245 R36.2@3271.5,305
ADC_3: C9.2 R37.2 U5.7 | length 620.6
  Top Layer w8: R37.2@3271.5,105 C9.2@3271.5,170 3320,170 3330,180 3430,180 3594.61,344.61 U5.7@3754.8,344.61
BINARY_1: C24.2 D4.1 D10.1 R3.2 R7.2 R24.1 R29.2 R75.2 | length 2798.6
  Top Layer w12: v1(2405,580) 2405,581.74 D4.1@2340.74,646 2326.21,660.53 D10.1@2326.21,740 2373,740 2430,797 2430,875 2465,910 2730,910 2770,870 2770,805 2795,780 ; R24.1@2795,736.5 2795,780 ; R29.2@2990,736.5 2990,790 2960,820 2835,820 2795,780
  Top Layer w20: R3.2@1021.5,610 v2(1082,610) R7.2@1133.5,610
  Bottom Layer w12: v2(1082,610) 1160,532 2357,532 v1(2405,580)
  Bottom Layer w20: R75.2@1022.5,670 1022.5,611 C24.2@1021.5,610 v2(1082,610)
BINARY_2: C25.2 D3.1 D11.1 R4.2 R8.2 R23.1 R30.1 R76.2 | length 2948.7
  Top Layer w12: D11.1@2305.21,472 2305.21,406.53 D3.1@2333.74,378 v1@2333.74,286.26 ; v1(2335,285) 2395,225 2395,140 2470,65 2772,65 2796,89 ; R23.1@2795,148.5 2796,147.5 2796,89 ; R30.1@2991,149.5 2991,91 2965,65 2820,65 2796,89
  Top Layer w20: R4.2@1021.5,95 v2(1073,95) R8.2@1133.5,95
  Bottom Layer w12: v2(1073,95) 1125.03,42.97 2317.97,42.97 2335,60 v1(2335,285)
  Bottom Layer w20: v2(1073,95) C25.2@1021.5,95 ; C25.2@1021.5,95 1021.5,158 C25.2@1021.5,95
GND: C1.1 C3.1 C5.1 C8.1 C9.1 C10.1 C11.1 C12.2 C13.2 C14.2 C15.1 C16.2 C17.2 C18.1 C21.2 C22.1 C23.1 C24.1 C25.1 D1.1 D2.1 D3.2 D4.2 D5.2 D7.2 D8.2 D10.2 D11.2 J1.3 L1.1 Q1.S Q2.S Q3.3 Q4.3 R3.1 R4.1 R11.1 R12.1 R14.1 R20.1 R21.1 R33.2 R34.1 R35.1 R42.1 R46.1 R50.1 R51.1 R53.1 R75.1 R76.1 T1.5 TP2.1 TP4.1 TP5.1 TP20.1 U1.2 U2.3 U3.11 U4.2 U5.20 | length 9542.8
  Top Layer w12: U3.11@2890,328.78 2890,385 2917.5,412.5 C5.1@3052,412.5 ; U5.20@3979.2,498.16 4037.84,498.16 v1(4053,483) 4104.5,483 4105.5,484
  Top Layer w15: D3.2@2176.26,378 2206.79,408.53 D11.2@2206.79,472 ; D4.2@2183.26,646 2227.79,690.53 D10.2@2227.79,740 ; C11.1@3248.5,570 3248.5,608.5 3250,610 v1(3250,615)
  Top Layer w20: TP5.1@850,95 R4.1@958.5,95 ; v2(905,610) R3.1@958.5,610 ; v2(1300,95) 1399.14,95 1436.14,132 ; v2(1305,585) 1393.5,585 1436.14,627.64 ; Q1.S@1436.14,230.24 1436.14,132 ; Q2.S@1436.14,725.24 1436.14,627.64 ; R12.1@2079,591.78 1472,591.78 1436.14,627.64 ; R12.1@2079,593.91 2131.17,593.91 D4.2@2183.26,646 2265.26,564 v1(2342,564) ; D3.2@2176.26,378 2176.26,321.74 2202,296 v1(2279,296) 2279,271 v1(2300,250) 2300,191.86 Q3.3@2306.8,185.06 2263.94,185.06 v1(2246,203) 2157,203 2122,238 1986,238 1928.91,180.91 R11.1@1928.91,117 1857,117 1833,93 1475.14,93 1436.14,132 ; v1(2475,730) R14.1@2475,778.5 ; v1(2495,575) 2525,575 2550,550 U1.2@2550,522.24 ; v1(2560.52,390.18) 2560.52,365.97 C1.1@2580,346.5 ; C3.1@2665,476.5 v1(2713.5,476.5) ; v1(2680,147.01) 2681.5,148.5 R20.1@2730,148.5 ; v1(2680,735) R21.1@2730,735 ; U2.3@2707.24,810 v1(2707.24,847.76) ; R34.1@3055,148.5 3103.5,148.5 v1(3105,150) ; R33.2@3055,736.5 v1(3055,785) ; R35.1@3167,933.5 3197.5,933.5 3205,941 v1(3232,941) ; v1(3200,720) C10.1@3248.5,720 ; C9.1@3208.5,170 3158.5,170 3140,188.5 v1(3140,220) 3140,225 3155,240 C8.1@3208.5,240 ; v1@3345,119.5 3392,119.5 R42.1@3392,124.5 ; v1@3413.36,856.64 v1(3413.36,860.64) 3455.62,860.64 D5.2@3486.62,891.64 3462.62,915.64 v1(3414.36,915.64) ; v1(3585,265) 3610,240 R46.1@3631.38,240 ; C14.2@3612,573 C14.2@3620.5,573 v1(3620.5,632.5) 3643.58,632.5 3668.58,657.5 3707.5,657.5 3770,595 v1(3770,550) ; C15.1@3620.5,508 C14.2@3620.5,564.5 ; C12.2@3746.36,894.13 3861.13,894.13 3909,942 v1(3950,942) ; v1(3964.98,745.02) C16.2@4011.82,745.02 ; C17.2@4014.82,678.02 4014.82,742.02 C16.2@4011.82,745.02 ; R50.1@4062,67.38 4171.62,67.38 v1(4175,64) ; U4.2@4078.56,850.02 4049.32,850.02 4034,834.71 4034,767.2 C16.2@4011.82,745.02 ; R51.1@4163.62,169 4182,150.62 v1(4182,127) ; v1(4219,65) 4220.09,63.91 L1.1@4285,63.91 ; v1(4240,429) 4241.5,427.5 C18.1@4241.5,380 ; v1(4345,664) 4345.5,664.5 T1.5@4345.5,725
  Top Layer w25: Q4.3@2317.8,932.06 2320.75,935 v1(2375,935) ; C5.1@3052,412.5 v1(3102.5,412.5)
  Top Layer w35: TP5.1@849.51,94.51 TP5.1@850,95
  Top Layer w80: TP4.1@310,105 569.51,105 D2.1@575,99.51 ; TP2.1@310,630 569.51,630 D1.1@575,624.51
  Bottom Layer w20: TP5.1@850,95 C25.1@957.5,95 958.5,95 958.5,196.5 968,206 1085.5,206 1196.5,95 v2(1300,95) 1305,90 C23.1@1398.5,90 ; v2(905,610) C24.1@958.5,610 958.5,669 959.5,670 959.5,707.5 976,724 1077,724 1216,585 v2(1305,585) 1393.5,585 C22.1@1398.5,590 ; D8.2@2243.44,593 2244.44,594 2244.44,585.56 2266,564 v1(2342,564) 2342,567.91 2395.09,621 2443,621 ; v1(2279,296) 2343,360 2430,360 ; v1@2560,390 2560.34,390 v1(2560.52,390.18)
  Bottom Layer w25: v1(2246,203) 2246,117.74 D7.2@2260.74,103 ; v1(2375,935) 2420,935 2425,940 ; v1@3100,415 v1(3102.5,412.5)
  Bottom Layer w40: TP4.1@310,105 725,105 730,100 845,100 TP5.1@850,95 ; TP2.1@310,630 635,630 655,610 v2(905,610)
  other v1: 3345,120
GND_ISO: C19.2 C20.2 D9.2 L2.2 TP25.1 TP29.1 U7.4 U7.5 | length 2210.4
  Top Layer w20: C20.2@4883,785.5 4974.99,877.49 5074.98,877.49 ; C19.2@4937.5,403 4992.25,457.75 4993,457 5016,457 5073.74,514.74 D9.2@5073.74,516 5310,516 v1(5311,515) ; L2.2@4991.09,76 5181,76 TP25.1@5185,80 ; 5052,877.49 5074.98,877.49 ; U7.4@5052.49,684.6 U7.5@5052.49,759.4 5165.4,759.4 5187,781 TP29.1@5187,880 5184.49,877.49 5074.98,877.49
  Bottom Layer w20: TP25.1@5195,80 TP25.1@5185,80 5314,209 5314,769 TP29.1@5203,880
NetC2_1: C2.1 R19.1 R39.1 TP8.1 U3.7 | length 1012.1
  Top Layer w8: C2.1@2665,539 R19.1@2730,539 2759,539 v1(2775,555) 2811.42,555 U3.7@2813.23,553.19 ; R39.1@3248.5,505 3248.5,466.5 3260,455 3300,455 TP8.1@3350,405
  Bottom Layer w8: v1(2775,555) 2855,555 2970,440 3015,440 3080,505 3250,505 TP8.1@3350,405
NetC2_2: C2.2 R19.2 R21.2 U3.6 | length 351
  Top Layer w8: C2.2@2665,601.99 R19.2@2730,601.99 R21.2@2730,673.5 2753.8,673.5 2762.3,665 2762.3,632.7 2770,625 2830,625 2838.82,616.18 U3.6@2838.82,553.19
NetC4_1: C4.1 R22.2 R37.1 TP14.1 U3.8 | length 1142
  Top Layer w8: C4.1@2667,348.5 R22.2@2731,348.5 2756.5,348.5 v1(2775,330) 2776.22,328.78 U3.8@2813.23,328.78 ; v1(3160,105) R37.1@3208.5,105 3208.5,71.5 3215,65 3296.72,65 3315,83.28 3315,135 3342,162 3472,162 3498,188 TP14.1@3552,188
  Bottom Layer w8: v1(2775,330) 2840,265 2926,265 3086,105 v1(3160,105)
NetC4_2: C4.2 R20.2 R22.1 U3.9 | length 335.2
  Top Layer w8: C4.2@2667,285.5 R22.1@2731,285.5 2731,212.5 R20.2@2730,211.5 2753.8,211.5 2762.3,220 2762.3,247.3 2780,265 2815,265 2838.82,288.82 U3.9@2838.82,328.78
NetC6_1: C6.1 R31.1 R38.1 TP9.1 U3.1 | length 685.4
  Top Layer w8: U3.1@2966.77,553.19 2991.81,553.19 3005.5,539.5 R31.1@3052,539.5 C6.1@3117,539.5 3149.5,539.5 3160,550 3160,640 3180,660 R38.1@3248.5,660 3288.5,620 3325,620 3415,530 TP9.1@3490,530
NetC6_2: C6.2 R31.2 R33.1 U3.2 | length 354.4
  Top Layer w8: U3.2@2941.18,553.19 2941.18,616.18 2955,630 3015,630 3022.7,637.7 3022.7,665.97 3030.24,673.5 R33.1@3055,673.5 3055,605.5 R31.2@3052,602.5 C6.2@3117,602.5
NetC7_1: C7.1 R32.1 R36.1 TP7.1 U3.14 | length 371.2
  Top Layer w8: U3.14@2966.77,328.78 2993.78,328.78 3013.5,348.5 R32.1@3052,348.5 C7.1@3117,348.5 3153.5,348.5 3208.5,403.5 R36.1@3208.5,305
